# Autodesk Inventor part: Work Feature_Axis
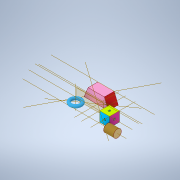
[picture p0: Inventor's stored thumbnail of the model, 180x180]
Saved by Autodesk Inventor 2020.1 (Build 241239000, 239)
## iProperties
Created: 2018-06
Part Number: Work Feature_Axis
Material: Generic
Document SubType Name: Modeling
Designer: Power User
Density: 1 g/cm^3
Appearance: Light Red
Author: Power User
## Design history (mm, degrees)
sketch "Sketch1"
  geometry: L1 (0, 0)-(50, 0); L2 (50, 0)-(50, -50); L3 (50, -50)-(0, -50); L4 (0, -50)-(0, 0); 1 further point
  constraints: 8 end point, 2 parallel, 1 coincident, 1 horizontal, 1 perpendicular
  dimensions: "d0" = 50 distance of L1.end L2.end; "d1" = 50 distance of L2.end L3.end; "d53" = 0 distance from line of point (0, 0) L4
extrude "Extrusion1" new body sketch "Sketch1" distance "d2" = 50; taper "d3" = 0 deg
workplane "Work Plane1"
sketch "Sketch2"
  geometry: L1 (0, 50)-(50, 50) reference; L2 (50, 0)-(50, 50) reference; C1 r 20 at (-30, 25); 3 further points
  constraints: 2 midpoint, 1 centre point, 1 horizontal alignment
  dimensions: "d5" = 40 diameter of C1; "d54" = 30 horizontal distance of C1.centre point (0, 0)
extrude "Extrusion2" new body sketch "Sketch2" distance "d6" = 50; taper "d7" = 0 deg
sketch "Sketch3"
  geometry: L1 (-172.16, 49.98)-(-172.16, 11.482); C1 r 7.5 at (-197.16, 26.587); 1 further point
  constraints: 2 end point, 1 centre point, 1 vertical
  dimensions: "d8" = 15 diameter of C1; "d9" = 50 diameter of C1.centre L1
revolve "Revolution1" sketch "Sketch3" stored, may be unused: angle "d10" = 90 deg
workplane "Work Plane2"
sketch "Sketch4"
  geometry: L1 (-98.807, 58.325)-(-98.807, 8.325); A1 r 25 centre (-98.807, 33.325) between (-98.807, 58.325) and (-98.807, 8.325); 1 further point
  constraints: 2 end point, 2 point on circle, 1 centre point, 1 vertical
  dimensions: "d12" = 50 diameter of A1
revolve "Revolution2" sketch "Sketch4" stored, may be unused: angle "d13" = 90 deg
workplane "Work Plane3"
sketch "Sketch5"
  geometry: L1 (-192.037, 9.98)-(-171.326, 59.98); L2 (-171.326, 59.98)-(-89.041, 59.98); L3 (-89.041, 59.98)-(-68.33, 9.98); L4 (-68.33, 9.98)-(-192.037, 9.98); L5 (-130.184, 59.98)-(-130.184, 9.98); 1 further point
  constraints: 10 end point, 2 midpoint, 1 horizontal, 1 parallel, 1 perpendicular, 1 other
  dimensions: "d15" = 50 distance between parallel lines of L4 L2; "d16" = 45 deg angle of L3 L1
extrude "Extrusion3" new body sketch "Sketch5" stored distance "d17" = 50; taper "d18" = 0 deg
sketch "Sketch6"
  geometry: L1 (15, 35)-(35, 35); L2 (35, 35)-(35, 15); L3 (35, 15)-(15, 15); L4 (15, 15)-(15, 35); L5 (0, 50)-(50, 50) reference; L6 (0, 0)-(0, 50) reference; 5 further points
  constraints: 4 midpoint, 1 horizontal alignment, 1 vertical alignment, 2 other
  dimensions: "d19" = 20 distance of L1.start L1.end; "d20" = 20 distance of L1.end L2.end
emboss "Emboss1" sketch "Sketch6" dims "d0" = 50, "d1" = 50, "d21" = 0.2, "d22" = 0, "d53" = 0
sketch "Sketch7"
  geometry: L1 (-35, 35)-(-15, 35); L2 (-15, 35)-(-15, 15); L3 (-15, 15)-(-35, 15); L4 (-35, 15)-(-35, 35); L5 (0, 50)-(-50, 50) reference; L6 (-50, 50)-(-50, 0) reference; 5 further points
  constraints: 4 midpoint, 1 horizontal alignment, 1 vertical alignment, 2 other
  dimensions: "d23" = 20 distance of L1.start L1.end; "d24" = 20 distance of L3.end L1.start
emboss "Emboss2" sketch "Sketch7" dims "d0" = 50, "d1" = 50, "d25" = 0.2, "d26" = 0, "d53" = 0
sketch "Sketch8"
  geometry: L1 (15, 35)-(35, 35); L2 (35, 35)-(35, 15); L3 (35, 15)-(15, 15); L4 (15, 15)-(15, 35); L5 (0, 0)-(0, 50) reference; L6 (0, 50)-(50, 50) reference; 4 further points
  constraints: 4 midpoint, 1 horizontal alignment, 1 vertical alignment, 2 other
  dimensions: "d27" = 20 distance of L1.start L1.end; "d28" = 20 distance of L3.end L1.start
emboss "Emboss3" sketch "Sketch8" dims "d0" = 50, "d1" = 50, "d29" = 0.2, "d30" = 0, "d53" = 0
sketch "Sketch9"
  geometry: L1 (-11.219, -35.018)-(-35.694, -35.018); L2 (-35.694, -35.018)-(-35.694, -14.982); L3 (-35.694, -14.982)-(-11.219, -14.982); L4 (-11.219, -14.982)-(-11.219, -35.018); L5 (0, -50)-(0, 0) reference; 4 further points
  constraints: 3 midpoint, 1 horizontal alignment, 1 vertical alignment, 2 other
emboss "Emboss4" sketch "Sketch9" dims "d0" = 50, "d1" = 50, "d31" = 0.2, "d32" = 0, "d53" = 0
sketch "Sketch10"
  geometry: L1 (15, 35)-(35, 35); L2 (35, 35)-(35, 15); L3 (35, 15)-(15, 15); L4 (15, 15)-(15, 35); L5 (0, 50)-(50, 50) reference; L6 (0, 0)-(0, 50) reference; 5 further points
  constraints: 4 midpoint, 1 horizontal alignment, 1 vertical alignment, 2 other
  dimensions: "d33" = 20 distance of L1.start L1.end; "d34" = 20 distance of L3.end L1.start
emboss "Emboss5" sketch "Sketch10" dims "d0" = 50, "d1" = 50, "d35" = 0.2, "d36" = 0, "d53" = 0
sketch "Sketch11"
  geometry: L1 (15, 35)-(35, 35); L2 (35, 35)-(35, 15); L3 (35, 15)-(15, 15); L4 (15, 15)-(15, 35); L5 (0, 0)-(0, 50) reference; L6 (0, 50)-(50, 50) reference; 4 further points
  constraints: 4 midpoint, 1 horizontal alignment, 1 vertical alignment, 2 other
  dimensions: "d37" = 20 distance of L1.start L1.end; "d38" = 20 distance of L1.end L2.end
emboss "Emboss6" sketch "Sketch11" dims "d0" = 50, "d1" = 50, "d39" = 0.2, "d40" = 0, "d53" = 0
sketch "Sketch12"
  geometry: L1 (118.439, 97.246)-(43.439, 97.246); L2 (43.439, 97.246)-(43.439, 172.246); L3 (43.439, 172.246)-(58.439, 172.246); L4 (58.439, 172.246)-(58.439, 112.246); L5 (58.439, 112.246)-(118.439, 112.246); L6 (118.439, 112.246)-(118.439, 97.246); 1 further point
  constraints: 12 end point, 4 perpendicular, 1 horizontal, 1 vertical
  dimensions: "d41" = 75 distance of L1.start L1.end; "d42" = 75 distance of L1.end L2.end (= d41); "d43" = 15 distance of L5.end L1.start; "d44" = 15 distance of L2.end L3.end (= d43)
extrude "Extrusion4" new body sketch "Sketch12" stored distance "d45" = 100; taper "d46" = 0 deg
sketch "Sketch13"
  geometry: L1 (97.246, 118.439)-(97.246, 43.439) reference; L2 (97.246, 43.439)-(172.246, 43.439) reference; L3 (172.246, 43.439)-(97.246, 43.439) reference; L4 (172.246, 118.439)-(97.246, 118.439); L5 (97.246, 118.439)-(97.246, 43.439); L6 (97.246, 43.439)-(172.246, 43.439); L7 (172.246, 43.439)-(172.246, 118.439); L8 (172.246, 118.439)-(97.246, 43.439); L9 (97.246, 118.439)-(172.246, 43.439); 2 further points
  constraints: 12 end point, 2 equal length, 2 midpoint, 2 parallel, 1 horizontal, 1 perpendicular
extrude "Extrusion5" join sketch "Sketch13" distance "d47" = 15; taper "d48" = 0 deg
feature "Move Body1"
workaxis "Work Axis1"
workaxis "Work Axis2"
workaxis "Work Axis3"
workaxis "Work Axis4"
workaxis "Work Axis5"
workaxis "Work Axis6"
workaxis "Work Axis7"
  workplane "Work Plane4"
workaxis "Work Axis8"
workaxis "Work Axis9"
workaxis "Work Axis10"
workaxis "Work Axis11"
workaxis "Work Axis12"
workaxis "Work Axis13"
node "Cube"
node "Cylinder"
node "Ring"
node "Sphere"
node "Trapezoid"
node "Solid"
other parameters: "d14" = -87.5
